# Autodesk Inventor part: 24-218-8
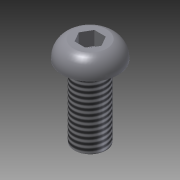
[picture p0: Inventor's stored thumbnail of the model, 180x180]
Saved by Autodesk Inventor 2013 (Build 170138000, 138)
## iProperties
Created: 2004-10
Part Number: 24-218-8
Material: Stahl (hohe Festigk., niedr. Legier.)
Document SubType Name: Modeling
Designer: Autodesk, Inc.
Manufacturer: Standard
Standards Organization: Custom
Description: SCREW, PARKER IPS, FLAT HEAD, M8X18
Catalog Web Link: http://www.parker.com/ead/cm1.asp?cmid=809
Vendor: PARKER IPS
Mass: 10.8823 g
Surface Area: 9.37524 cm^2
Volume: 1.38805 cm^3
Density: 7.84 g/cm^3
CAGE: 1LJX3
Dept. ID: Product Design
Description #2: ---
Finish #1: ---
Finish #2: ---
Material ID: ---
Project Number: ---
Author: Autodesk, Inc.
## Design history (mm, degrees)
derived "2X-YYY-ZZ IPS Screws.ipt"
body "Solid1"
tag "TaggingFeature2"
feature "Solid1::2X-YYY-ZZ IPS Screws.ipt" dims "ScaleForDerivedMember" = 10
